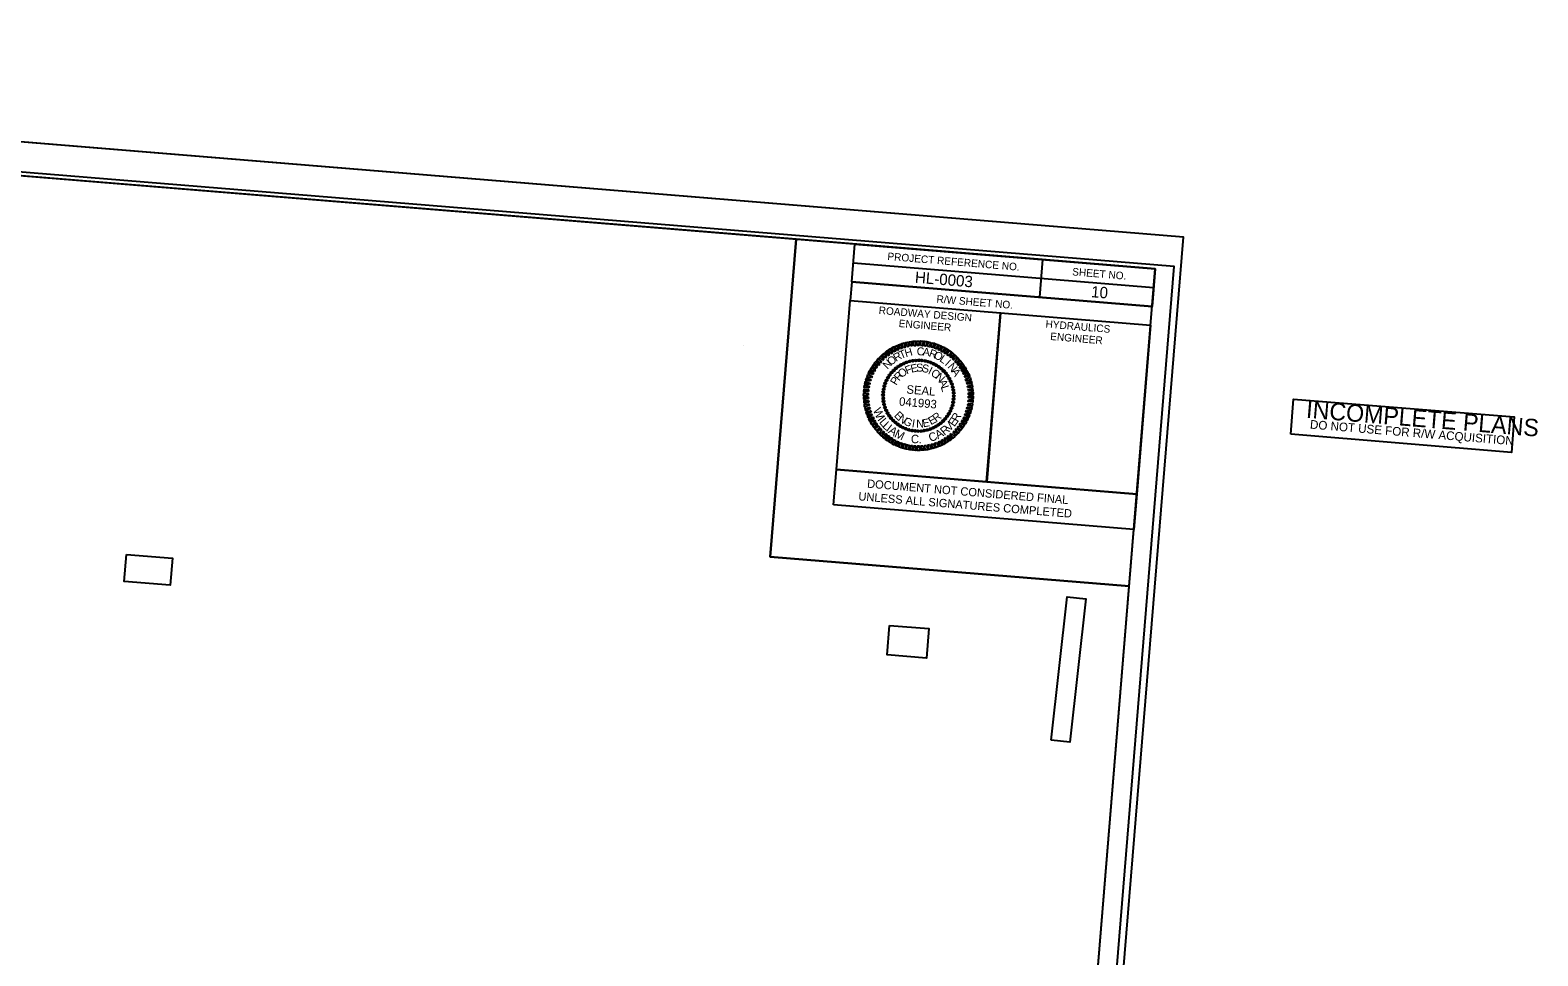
# Model space of a CAD drawing. Extents: x 935643 to 937646, y 683795 to 685023.
# Drawn here: x 936645 to 937646, y 684409 to 685023 of the extents above; entities that cross this region are included whole.
import ezdxf

# ---------------------------------------------------------------- set-up
doc = ezdxf.new("R2010")
doc.units = 0
for name, color, linetype in [('Default', 7, 'Continuous'), ('Sheet Cutting Line CELL', 7, 'Continuous'), ('Sheet Data Field CELL', 7, 'Continuous'), ('Sheet North Arrow Point CELL', 7, 'Continuous'), ('Sheet Plan CELL', 7, 'Continuous'), ('Sheet Plan Layout CELL', 7, 'Continuous'), ('Sheet Plot Border Inside CELL', 7, 'Continuous'), ('Sheet Plot Border Outside CELL', 7, 'Continuous'), ('Typical Text Grade Point CELL', 7, 'Continuous')]:
    doc.layers.add(name, color=color, linetype=linetype)

msp = doc.modelspace()

# ---------------------------------------------------------------- linework, layer by layer
at = {"layer": 'Default'}
for p, q in [((937221.3, 684800.2), (937221.3, 684800.2)), ((937223.1, 684801.2), (937223.1, 684801.2)), ((937224.9, 684802.1), (937224.9, 684802.1)), ((937226.8, 684802.9), (937226.8, 684802.9)), ((937228.8, 684803.5), (937228.8, 684803.5)), ((937230.8, 684803.9), (937230.8, 684803.9)), ((937232.9, 684804.1), (937232.9, 684804.1)), ((937234.9, 684804.2), (937234.9, 684804.2)), ((937237, 684804.1), (937237, 684804.1)), ((937239, 684803.8), (937239, 684803.8)), ((937241, 684803.3), (937241, 684803.3)), ((937242.9, 684802.7), (937242.9, 684802.7)), ((937244.8, 684801.9), (937244.8, 684801.9)), ((937246.6, 684800.9), (937246.6, 684800.9)), ((937248.4, 684799.8), (937248.4, 684799.8)), ((937212.6, 684789), (937212.6, 684789)), ((937213.4, 684790.9), (937213.4, 684790.9)), ((937214.4, 684792.7), (937214.4, 684792.7)), ((937215.5, 684794.4), (937215.5, 684794.4)), ((937216.8, 684796), (937216.8, 684796)), ((937218.2, 684797.6), (937218.2, 684797.6)), ((937219.7, 684798.9), (937219.7, 684798.9)), ((937250, 684798.5), (937250, 684798.5)), ((937251.5, 684797.1), (937251.5, 684797.1)), ((937252.8, 684795.6), (937252.8, 684795.6)), ((937254.1, 684794), (937254.1, 684794)), ((937255.1, 684792.2), (937255.1, 684792.2)), ((937256.1, 684790.4), (937256.1, 684790.4)), ((937211.1, 684781), (937211.1, 684781)), ((937211.2, 684783), (937211.2, 684783)), ((937211.5, 684785.1), (937211.5, 684785.1)), ((937212, 684787.1), (937212, 684787.1)), ((937234.6, 684780.7), (937234.6, 684780.7)), ((937256.8, 684788.5), (937256.8, 684788.5)), ((937257.4, 684786.5), (937257.4, 684786.5)), ((937257.8, 684784.5), (937257.8, 684784.5)), ((937258, 684782.4), (937258, 684782.4)), ((937258.2, 684780.4), (937258.2, 684780.4)), ((937211.2, 684778.9), (937211.2, 684778.9)), ((937211.4, 684776.8), (937211.4, 684776.8)), ((937211.8, 684774.8), (937211.8, 684774.8)), ((937212.4, 684772.9), (937212.4, 684772.9)), ((937213.2, 684771), (937213.2, 684771)), ((937214.1, 684769.1), (937214.1, 684769.1)), ((937255.8, 684770.5), (937255.8, 684770.5)), ((937256.7, 684772.4), (937256.7, 684772.4)), ((937257.2, 684774.3), (937257.2, 684774.3)), ((937257.7, 684776.3), (937257.7, 684776.3)), ((937258, 684778.3), (937258, 684778.3)), ((937215.1, 684767.4), (937215.1, 684767.4)), ((937216.4, 684765.8), (937216.4, 684765.8)), ((937217.8, 684764.2), (937217.8, 684764.2)), ((937219.3, 684762.8), (937219.3, 684762.8)), ((937220.9, 684761.5), (937220.9, 684761.5)), ((937222.6, 684760.5), (937222.6, 684760.5)), ((937224.4, 684759.5), (937224.4, 684759.5)), ((937244.3, 684759.2), (937244.3, 684759.2)), ((937246.2, 684760.2), (937246.2, 684760.2)), ((937247.9, 684761.2), (937247.9, 684761.2)), ((937249.5, 684762.5), (937249.5, 684762.5)), ((937251.1, 684763.8), (937251.1, 684763.8)), ((937252.5, 684765.4), (937252.5, 684765.4)), ((937253.8, 684766.9), (937253.8, 684766.9)), ((937254.8, 684768.7), (937254.8, 684768.7)), ((937226.3, 684758.6), (937226.3, 684758.6)), ((937228.3, 684758.1), (937228.3, 684758.1)), ((937230.2, 684757.6), (937230.2, 684757.6)), ((937232.3, 684757.3), (937232.3, 684757.3)), ((937234.3, 684757.1), (937234.3, 684757.1)), ((937236.4, 684757.3), (937236.4, 684757.3)), ((937238.5, 684757.5), (937238.5, 684757.5)), ((937240.5, 684757.9), (937240.5, 684757.9)), ((937242.4, 684758.5), (937242.4, 684758.5))]:
    msp.add_line(p, q, dxfattribs=at)
for points in [[(937214.4, 684807.2), (937212.5, 684809.4), (937213.7, 684810.5), (937215.3, 684807.8)], [(937216.4, 684808.5), (937214.6, 684810.9), (937215.9, 684811.8), (937217.3, 684809.1)], [(937218.3, 684809.8), (937216.7, 684812.3), (937218, 684813.1), (937219.4, 684810.2)], [(937220.4, 684810.8), (937218.9, 684813.4), (937220.4, 684814.1), (937221.4, 684811.3)], [(937222.5, 684811.7), (937221.3, 684814.5), (937222.8, 684815), (937223.6, 684812.1)], [(937224.7, 684812.5), (937223.7, 684815.4), (937225.1, 684815.8), (937225.9, 684812.7)], [(937227, 684813.1), (937226.2, 684816), (937227.7, 684816.3), (937228, 684813.3)], [(937229.3, 684813.5), (937228.6, 684816.5), (937230.2, 684816.7), (937230.3, 684813.7)], [(937231.6, 684813.9), (937231.1, 684816.9), (937232.6, 684816.9), (937232.7, 684813.9)], [(937233.9, 684814), (937233.6, 684817), (937235.2, 684817), (937235, 684814)], [(937236.2, 684814), (937236.2, 684817.1), (937237.8, 684816.9), (937237.3, 684813.9)], [(937238.5, 684813.8), (937238.7, 684816.8), (937240.2, 684816.6), (937239.6, 684813.6)], [(937240.8, 684813.4), (937241.2, 684816.5), (937242.7, 684816), (937241.9, 684813.2)], [(937243, 684812.9), (937243.7, 684815.8), (937245.2, 684815.5), (937244.1, 684812.6)], [(937245.3, 684812.2), (937246, 684815.2), (937247.6, 684814.7), (937246.3, 684811.9)], [(937247.5, 684811.4), (937248.5, 684814.2), (937249.9, 684813.6), (937248.5, 684811)], [(937249.6, 684810.4), (937250.9, 684813.2), (937252.1, 684812.6), (937250.6, 684809.9)], [(937251.6, 684809.3), (937253, 684812), (937254.4, 684811.2), (937252.6, 684808.7)], [(937253.6, 684808.1), (937255.1, 684810.6), (937256.5, 684809.7), (937254.5, 684807.4)], [(937255.4, 684806.6), (937257.2, 684809.2), (937258.4, 684808.1), (937256.3, 684806)], [(937205.4, 684796.7), (937202.6, 684798), (937203.5, 684799.4), (937206, 684797.7)], [(937206.6, 684798.7), (937204, 684800.1), (937204.8, 684801.5), (937207.2, 684799.6)], [(937207.8, 684800.7), (937205.3, 684802.3), (937206.4, 684803.5), (937208.7, 684801.4)], [(937209.4, 684802.4), (937207, 684804.2), (937208, 684805.5), (937210.1, 684803.2)], [(937210.9, 684804.1), (937208.7, 684806.1), (937209.8, 684807.2), (937211.7, 684804.9)], [(937212.7, 684805.7), (937210.5, 684807.8), (937211.8, 684808.8), (937213.5, 684806.4)], [(937257.2, 684805.1), (937259.1, 684807.5), (937260.2, 684806.4), (937258, 684804.4)], [(937258.8, 684803.5), (937260.9, 684805.8), (937262, 684804.6), (937259.7, 684802.7)], [(937260.4, 684801.7), (937262.6, 684803.8), (937263.6, 684802.5), (937261, 684800.9)], [(937261.9, 684799.9), (937264.2, 684801.8), (937265.1, 684800.5), (937262.4, 684798.9)], [(937263.1, 684798), (937265.6, 684799.7), (937266.3, 684798.3), (937263.6, 684797)], [(937202.1, 684788), (937199.1, 684788.5), (937199.5, 684790.1), (937202.4, 684789.1)], [(937202.7, 684790.3), (937199.8, 684790.9), (937200.3, 684792.5), (937203.1, 684791.3)], [(937203.5, 684792.5), (937200.6, 684793.3), (937201.1, 684794.9), (937203.9, 684793.5)], [(937204.3, 684794.7), (937201.5, 684795.8), (937202.2, 684797.2), (937204.9, 684795.6)], [(937264.2, 684796), (937266.8, 684797.5), (937267.6, 684796), (937264.8, 684795)], [(937265.2, 684793.8), (937268, 684795.2), (937268.5, 684793.7), (937265.7, 684792.9)], [(937266, 684791.7), (937268.9, 684792.9), (937269.4, 684791.3), (937266.4, 684790.6)], [(937266.7, 684789.4), (937269.6, 684790.4), (937270, 684788.9), (937267, 684788.4)], [(937201.3, 684781.1), (937198.2, 684780.9), (937198.3, 684782.5), (937201.3, 684782.2)], [(937201.4, 684778.8), (937198.3, 684778.4), (937198.3, 684780), (937201.3, 684779.9)], [(937201.4, 684783.4), (937198.4, 684783.5), (937198.5, 684785.1), (937201.5, 684784.5)], [(937201.7, 684785.7), (937198.7, 684786.1), (937198.9, 684787.6), (937201.9, 684786.8)], [(937267.2, 684787.1), (937270.3, 684788), (937270.5, 684786.4), (937267.5, 684786.1)], [(937267.6, 684784.9), (937270.6, 684785.5), (937270.8, 684783.9), (937267.8, 684783.9)], [(937267.8, 684782.6), (937270.9, 684783), (937270.9, 684781.4), (937267.9, 684781.4)], [(937267.9, 684780.3), (937271, 684780.4), (937271, 684778.8), (937267.9, 684779.2)], [(937201.6, 684776.5), (937198.6, 684775.9), (937198.5, 684777.5), (937201.4, 684777.5)], [(937202, 684774.2), (937198.9, 684773.4), (937198.8, 684775), (937201.8, 684775.2)], [(937202.6, 684771.9), (937199.6, 684770.9), (937199.2, 684772.4), (937202.2, 684772.9)], [(937203.2, 684769.7), (937200.4, 684768.5), (937199.9, 684770), (937202.9, 684770.7)], [(937266.6, 684771.1), (937269.4, 684770.5), (937269, 684768.9), (937266.1, 684770.1)], [(937267.1, 684773.4), (937270.1, 684772.9), (937269.8, 684771.3), (937266.8, 684772.3)], [(937267.6, 684775.6), (937270.6, 684775.3), (937270.4, 684773.8), (937267.4, 684774.5)], [(937267.8, 684778), (937270.8, 684777.9), (937270.7, 684776.3), (937267.7, 684776.9)], [(937204, 684767.6), (937201.3, 684766.2), (937200.8, 684767.7), (937203.5, 684768.5)], [(937205.1, 684765.4), (937202.4, 684763.8), (937201.7, 684765.3), (937204.5, 684766.4)], [(937206.1, 684763.4), (937203.7, 684761.6), (937202.9, 684763.1), (937205.6, 684764.3)], [(937207.4, 684761.5), (937205, 684759.5), (937204.2, 684760.9), (937206.8, 684762.5)], [(937208.9, 684759.7), (937206.7, 684757.6), (937205.6, 684758.8), (937208.2, 684760.5)], [(937259.8, 684759), (937262.2, 684757.2), (937261.2, 684755.9), (937259.2, 684758.1)], [(937261.4, 684760.7), (937263.9, 684759.1), (937262.9, 684757.9), (937260.6, 684759.9)], [(937262.7, 684762.6), (937265.2, 684761.2), (937264.4, 684759.9), (937262, 684761.8)], [(937263.8, 684764.7), (937266.6, 684763.4), (937265.8, 684762), (937263.2, 684763.7)], [(937264.9, 684766.7), (937267.7, 684765.6), (937267, 684764.2), (937264.3, 684765.7)], [(937265.8, 684768.9), (937268.6, 684768), (937268.2, 684766.5), (937265.3, 684767.9)], [(937210.4, 684757.9), (937208.3, 684755.6), (937207.3, 684756.8), (937209.6, 684758.7)], [(937212.1, 684756.3), (937210.1, 684753.9), (937209, 684755), (937211.2, 684757)], [(937213.9, 684754.7), (937212, 684752.2), (937210.9, 684753.2), (937212.9, 684755.4)], [(937215.6, 684753.3), (937214.1, 684750.8), (937212.8, 684751.7), (937214.7, 684754)], [(937217.6, 684752.1), (937216.3, 684749.4), (937214.9, 684750.2), (937216.7, 684752.7)], [(937219.7, 684751), (937218.4, 684748.2), (937217.1, 684748.8), (937218.6, 684751.4)], [(937221.7, 684750), (937220.8, 684747.2), (937219.4, 684747.7), (937220.8, 684750.4)], [(937223.9, 684749.2), (937223.2, 684746.2), (937221.6, 684746.7), (937222.9, 684749.5)], [(937246.7, 684749.6), (937248, 684746.9), (937246.5, 684746.4), (937245.6, 684749.3)], [(937248.8, 684750.6), (937250.3, 684747.9), (937248.8, 684747.3), (937247.9, 684750.1)], [(937251, 684751.6), (937252.5, 684749.1), (937251.2, 684748.3), (937249.9, 684751.1)], [(937252.8, 684752.9), (937254.7, 684750.5), (937253.3, 684749.6), (937251.9, 684752.3)], [(937254.8, 684754.2), (937256.7, 684751.9), (937255.5, 684750.9), (937253.9, 684753.6)], [(937256.5, 684755.7), (937258.7, 684753.6), (937257.5, 684752.6), (937255.7, 684755)], [(937258.3, 684757.3), (937260.6, 684755.3), (937259.4, 684754.2), (937257.6, 684756.5)], [(937226.2, 684748.5), (937225.6, 684745.5), (937224.1, 684745.9), (937225.1, 684748.7)], [(937228.5, 684747.9), (937228, 684744.9), (937226.5, 684745.3), (937227.4, 684748.2)], [(937230.8, 684747.6), (937230.5, 684744.6), (937229, 684744.7), (937229.7, 684747.7)], [(937233, 684747.4), (937233, 684744.3), (937231.5, 684744.5), (937231.9, 684747.5)], [(937235.4, 684747.4), (937235.6, 684744.4), (937234, 684744.3), (937234.2, 684747.4)], [(937237.6, 684747.5), (937238.1, 684744.5), (937236.6, 684744.5), (937236.5, 684747.5)], [(937239.9, 684747.8), (937240.7, 684744.8), (937239.1, 684744.6), (937238.9, 684747.7)], [(937242.2, 684748.3), (937243.1, 684745.4), (937241.6, 684745.1), (937241.2, 684748)], [(937244.6, 684748.8), (937245.6, 684746), (937244.1, 684745.6), (937243.4, 684748.6)]]:
    msp.add_lwpolyline(points, close=True, dxfattribs=at)
for centre, major_axis in [((937219.7, 684798.9), (-0.428, 0.522)), ((937221.4, 684800.1), (-0.381, 0.557)), ((937223.1, 684801.2), (-0.331, 0.589)), ((937224.9, 684802.1), (-0.278, 0.615)), ((937226.8, 684802.9), (-0.223, 0.637)), ((937228.8, 684803.5), (-0.167, 0.654)), ((937230.8, 684803.9), (-0.109, 0.666)), ((937232.8, 684804.1), (-0.051, 0.673)), ((937234.9, 684804.2), (0.008, 0.675)), ((937236.9, 684804.1), (0.067, 0.672)), ((937239, 684803.8), (0.125, 0.663)), ((937241, 684803.3), (0.182, 0.65)), ((937242.9, 684802.7), (0.238, 0.632)), ((937244.8, 684801.9), (0.292, 0.608)), ((937246.6, 684800.9), (0.344, 0.581)), ((937248.3, 684799.8), (0.394, 0.548)), ((937249.9, 684798.5), (0.44, 0.512)), ((937212.6, 684789), (-0.632, 0.238)), ((937213.4, 684790.9), (-0.608, 0.292)), ((937214.4, 684792.7), (-0.581, 0.344)), ((937215.5, 684794.4), (-0.548, 0.394)), ((937216.8, 684796), (-0.512, 0.44)), ((937218.2, 684797.5), (-0.472, 0.483)), ((937251.4, 684797.1), (0.483, 0.472)), ((937252.8, 684795.6), (0.522, 0.428)), ((937254, 684793.9), (0.557, 0.381)), ((937255.1, 684792.2), (0.589, 0.331)), ((937256, 684790.4), (0.615, 0.278)), ((937256.8, 684788.5), (0.637, 0.223)), ((937211.1, 684781), (-0.675, 0.008)), ((937211.2, 684783), (-0.672, 0.067)), ((937211.2, 684778.9), (-0.673, -0.051)), ((937211.5, 684785), (-0.663, 0.125)), ((937212, 684787), (-0.65, 0.182)), ((937257.4, 684786.5), (0.654, 0.167)), ((937257.8, 684784.5), (0.666, 0.109)), ((937258, 684778.4), (0.672, -0.067)), ((937258.1, 684782.5), (0.673, 0.051)), ((937258.1, 684780.4), (0.675, -0.008)), ((937211.4, 684776.9), (-0.666, -0.109)), ((937211.8, 684774.9), (-0.654, -0.167)), ((937212.4, 684772.9), (-0.637, -0.223)), ((937213.2, 684771), (-0.615, -0.278)), ((937214.1, 684769.2), (-0.589, -0.331)), ((937254.8, 684768.7), (0.581, -0.344)), ((937255.8, 684770.5), (0.608, -0.292)), ((937256.6, 684772.4), (0.632, -0.238)), ((937257.3, 684774.3), (0.65, -0.182)), ((937257.7, 684776.3), (0.663, -0.125)), ((937215.2, 684767.4), (-0.557, -0.381)), ((937216.4, 684765.8), (-0.522, -0.428)), ((937217.8, 684764.3), (-0.483, -0.472)), ((937219.3, 684762.9), (-0.44, -0.512)), ((937220.9, 684761.6), (-0.394, -0.548)), ((937222.6, 684760.5), (-0.344, -0.581)), ((937224.4, 684759.5), (-0.292, -0.608)), ((937226.3, 684758.7), (-0.238, -0.632)), ((937242.4, 684758.5), (0.223, -0.637)), ((937244.3, 684759.3), (0.278, -0.615)), ((937246.1, 684760.2), (0.331, -0.589)), ((937247.9, 684761.3), (0.381, -0.557)), ((937249.5, 684762.5), (0.428, -0.522)), ((937251, 684763.9), (0.472, -0.483)), ((937252.4, 684765.4), (0.512, -0.44)), ((937253.7, 684767), (0.548, -0.394)), ((937228.3, 684758), (-0.182, -0.65)), ((937230.3, 684757.6), (-0.125, -0.663)), ((937232.3, 684757.3), (-0.067, -0.672)), ((937234.3, 684757.2), (-0.008, -0.675)), ((937236.4, 684757.2), (0.051, -0.673)), ((937238.4, 684757.5), (0.109, -0.666)), ((937240.4, 684757.9), (0.167, -0.654))]:
    msp.add_ellipse(centre, major_axis=major_axis, ratio=0.999708, dxfattribs=at)
at = {"layer": 'Sheet Cutting Line CELL'}
msp.add_line((937410.6, 684886), (935732.7, 685023.3), dxfattribs=at)
at = {"layer": 'Sheet North Arrow Point CELL'}
msp.add_line((937118.7, 684814.1), (937118.7, 684814.1), dxfattribs=at)
at = {"layer": 'Sheet Plan CELL'}
for p, q in [((937317, 684871), (937315.1, 684846.1)), ((937191.4, 684868.8), (937390.8, 684852.5)), ((937190.4, 684856.3), (937189.4, 684843.8)), ((937190.4, 684856.3), (937389.8, 684840)), ((937190.4, 684856.3), (937389.8, 684840)), ((937289.1, 684835.7), (937280, 684723.6)), ((937178.3, 684708.3), (937180.2, 684731.7)), ((937180.2, 684731.7), (937379.6, 684715.4)), ((937379.6, 684715.4), (937377.7, 684692)), ((937377.7, 684692), (937178.3, 684708.3))]:
    msp.add_line(p, q, dxfattribs=at)
for points in [[(937391.9, 684865), (935896.8, 684987.3), (935811.2, 683940.8), (937306.2, 683818.5)], [(937192.5, 684881.3), (937391.9, 684865), (937389.8, 684840), (937190.4, 684856.3)], [(937189.4, 684843.8), (937289.1, 684835.7), (937279.9, 684723.5), (937180.2, 684731.7)], [(937289.1, 684835.7), (937388.8, 684827.5), (937379.6, 684715.4), (937279.9, 684723.5)], [(937481.9, 684755.1), (937483.8, 684778.5), (937630.3, 684766.6), (937628.4, 684743.1)]]:
    msp.add_lwpolyline(points, close=True, dxfattribs=at)
at = {"layer": 'Sheet Plan Layout CELL'}
for points in [[(935896.8, 684987.3), (935811.2, 683940.8), (937306.2, 683818.5), (937374.6, 684654.2), (937136.1, 684673.7), (937153.4, 684884.5)], [(937136.1, 684673.7), (937374.6, 684654.2), (937391.9, 684865), (937153.4, 684884.5)]]:
    msp.add_lwpolyline(points, close=True, dxfattribs=at)
at = {"layer": 'Sheet Plot Border Inside CELL'}
msp.add_lwpolyline([(935658, 683950.8), (937318.5, 683815), (937404.5, 684866.4), (935744.1, 685002.3)], close=True, dxfattribs=at)
at = {"layer": 'Sheet Plot Border Outside CELL'}
msp.add_lwpolyline([(935643.4, 683931.9), (937321.3, 683794.6), (937410.6, 684886), (935732.7, 685023.3)], close=True, dxfattribs=at)
at = {"layer": 'Typical Text Grade Point CELL'}
for points in [[(936708.7, 684675.4), (936739.3, 684672.9), (936737.8, 684654.9), (936707.2, 684657.4)], [(937322.8, 684552.1), (937333.4, 684647.2), (937345.7, 684645.8), (937335.2, 684550.7)], [(937215.4, 684628.3), (937241.6, 684626.2), (937240, 684606.6), (937213.8, 684608.7)]]:
    msp.add_lwpolyline(points, close=True, dxfattribs=at)

# ---------------------------------------------------------------- texts
at = {"layer": 'Default'}
for s, height, rotation, p in [('R', 5.29, 30.3426, (937219.8, 684803.1)), ('T', 5.29, 23.1419, (937223.1, 684804.9)), ('H', 5.29, 15.9416, (937226.3, 684806.2)), ('C', 5.29, 1.542, (937233.6, 684807.4)), ('A', 5.29, 354.3424, (937237.3, 684807.4)), ('R', 5.29, 339.9432, (937241.2, 684806.9)), ('O', 5.29, 332.7433, (937244.3, 684806)), ('N', 5.29, 44.7456, (937214, 684797.9)), ('O', 5.29, 37.5439, (937216.3, 684800.4)), ('F', 5.29, 21.2891, (937226.9, 684794.8)), ('E', 5.29, 11.9332, (937230, 684795.9)), ('S', 5.29, 2.5777, (937233.3, 684796.6)), ('S', 5.29, 353.2225, (937236.7, 684796.4)), ('I', 5.29, 334.5117, (937240.6, 684795.4)), ('L', 5.29, 325.543, (937248.2, 684803.9)), ('I', 5.29, 318.3423, (937251.8, 684801.3)), ('N', 5.29, 311.141, (937253.7, 684799.7)), ('P', 5.29, 58.721, (937220, 684787.2)), ('R', 5.29, 49.3618, (937221.8, 684790.1)), ('O', 5.29, 40.0034, (937223.6, 684792.3)), ('O', 5.29, 325.1556, (937242.4, 684794.6)), ('N', 5.29, 315.7987, (937245.4, 684792.5)), ('A', 5.29, 297.0824, (937247.9, 684789.9)), ('A', 5.29, 303.9393, (937256.2, 684796.7)), ('041993', 5.62, 355.3221, (937221.6, 684774.2)), ('SEAL', 5.62, 355.3221, (937226.5, 684782.2)), ('L', 5.29, 287.723, (937249.4, 684786.5)), ('W', 5.62, 293.6795, (937204.3, 684771.2)), ('E', 5.29, 313.599, (937218.1, 684767.3)), ('R', 5.29, 37.8035, (937246.4, 684763)), ('R', 5.62, 62.0185, (937260.9, 684762.8)), ('I', 5.62, 306.2136, (937207.1, 684764.8)), ('L', 5.62, 310.0155, (937208.2, 684763)), ('L', 5.62, 316.2903, (937210.3, 684760.2)), ('I', 5.62, 322.5651, (937212.7, 684757.7)), ('A', 5.62, 326.367, (937214.2, 684756.3)), ('N', 5.29, 322.9561, (937220.7, 684764.6)), ('G', 5.29, 332.3124, (937224.1, 684762.2)), ('I', 5.29, 351.0233, (937230, 684759.9)), ('N', 5.29, 0.3785, (937233.2, 684759.5)), ('E', 5.29, 9.7339, (937237.8, 684759.7)), ('E', 5.29, 28.4462, (937242.9, 684761.1)), ('R', 5.62, 39.1759, (937251.9, 684754)), ('V', 5.62, 46.6562, (937255.2, 684756.5)), ('E', 5.62, 54.9092, (937258.5, 684759.7)), ('M', 5.62, 335.2073, (937218.2, 684753.5)), ('C', 5.62, 356.9372, (937229.5, 684749.3)), ('.', 5.62, 6.5193, (937234.8, 684748.9)), ('C', 5.62, 20.7535, (937242.6, 684749.9)), ('A', 5.62, 30.3356, (937247.6, 684751.7))]:
    msp.add_text(s, height=height, rotation=rotation, dxfattribs=at).set_placement(p)
at = {"layer": 'Sheet Data Field CELL'}
for s, p in [('HL-0003', (937232.1, 684855.7)), ('10', (937349.1, 684846.1))]:
    msp.add_text(s, height=7.5, rotation=355.3221, dxfattribs=at).set_placement(p)
at = {"layer": 'Sheet Plan CELL'}
for s, height, p in [('PROJECT REFERENCE NO.', 5, (937213.9, 684870.8)), ('SHEET NO.', 5, (937336.6, 684860.6)), ('ROADWAY DESIGN', 5, (937208.1, 684835)), ('R/W SHEET NO.', 5, (937246.5, 684842.5)), ('ENGINEER', 5, (937221.4, 684826.3)), ('HYDRAULICS', 5, (937318.9, 684825.9)), ('ENGINEER', 5, (937322, 684817.7)), ('INCOMPLETE PLANS', 11.52, (937491.8, 684766.1)), ('DO NOT USE FOR R/W ACQUISITION', 5.76, (937494.5, 684758.9)), ('DOCUMENT NOT CONSIDERED FINAL', 5.5, (937200.4, 684719.7)), ('UNLESS ALL SIGNATURES COMPLETED', 5.5, (937194.6, 684711.3))]:
    msp.add_text(s, height=height, rotation=355.3221, dxfattribs=at).set_placement(p)

doc.saveas('drawing.dxf')
